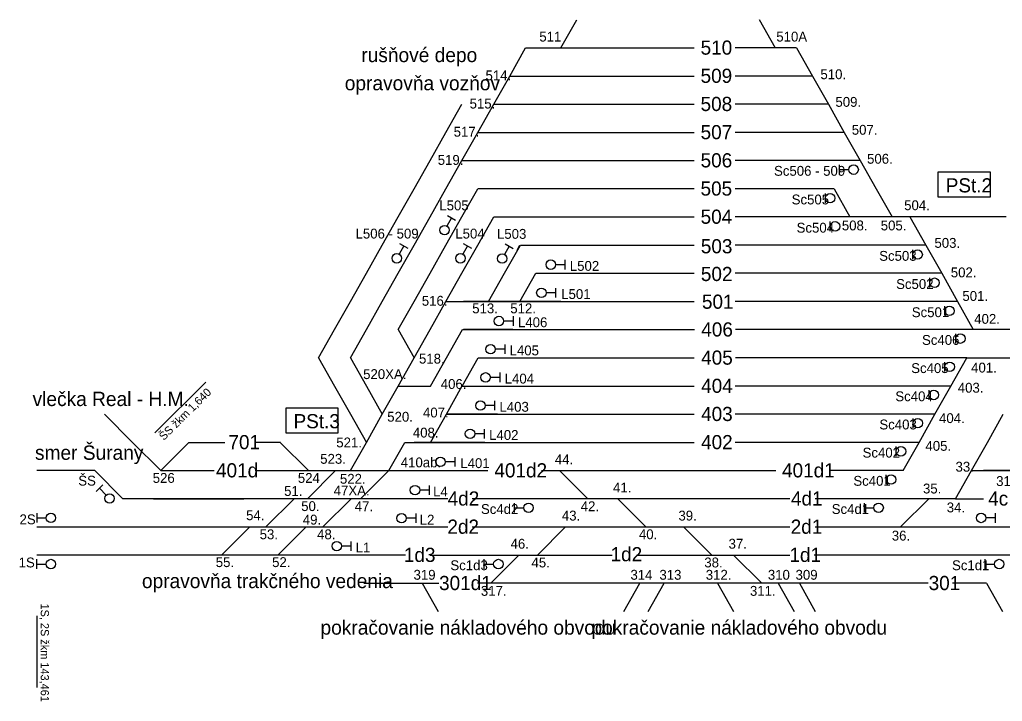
# Model space of a CAD drawing. Extents: x -119 to 851, y -238 to 59.
# Drawn here: x -82.9 to -13.2, y -186.9 to -138.5 of the extents above; entities that cross this region are included whole.
import ezdxf

# ---------------------------------------------------------------- set-up
doc = ezdxf.new("R2010")
doc.units = 0
for name, color, linetype in [('budova', 7, 'Continuous'), ('Level 2', 7, 'Continuous'), ('netlač', 7, 'Continuous'), ('popisky navestidla', 7, 'Continuous'), ('PU_navestidla', 7, 'Continuous'), ('PU_oznacenie navestidiel', 7, 'Continuous'), ('PU_stan_kolaje', 7, 'Continuous'), ('PU_vlecky', 7, 'Continuous')]:
    doc.layers.add(name, color=color, linetype=linetype)

msp = doc.modelspace()

# ---------------------------------------------------------------- linework, layer by layer
at = {"layer": 'budova'}
for points in [[(-17.784, -151.091), (-14.056, -151.091), (-14.056, -149.343), (-17.784, -149.343)], [(-64.061, -167.819), (-60.333, -167.819), (-60.333, -166.071), (-64.061, -166.071)]]:
    msp.add_lwpolyline(points, close=True, dxfattribs=at)
at = {"layer": 'Level 2'}
for p, q in [((-12.948, -152.506), (-19.775, -152.506)), ((-44.541, -158.502), (-51.44, -158.502)), ((-47.94, -160.501), (-51.44, -160.501)), ((-49.04, -166.498), (-52.662, -166.498)), ((-64.438, -168.497), (-66.22, -168.497)), ((-54.839, -168.497), (-54.939, -168.497)), ((-49.94, -168.497), (-54.839, -168.497)), ((-66.22, -170.496), (-60.529, -170.496)), ((-8.646, -170.496), (-14.545, -170.496)), ((-73.436, -172.495), (-67.037, -172.495)), ((-16.535, -172.495), (-14.54, -172.495)), ((-81.735, -174.494), (-52.567, -174.494)), ((-50.844, -174.494), (-28.284, -174.494)), ((-26.494, -174.494), (-2.882, -174.494)), ((-58.513, -178.492), (-53.203, -178.492)), ((-14.342, -178.492), (-16.745, -178.492))]:
    msp.add_line(p, q, dxfattribs=at)
for points in [[(-47.644, -154.87), (-47.44, -154.504)], [(-77.613, -170.496), (-81.735, -170.496)]]:
    msp.add_lwpolyline(points, dxfattribs=at)
at = {"layer": 'netlač'}
for p, q in [((-47.042, -140.518), (-35.082, -140.518)), ((-27.82, -140.515), (-32.169, -140.515)), ((-48.172, -142.517), (-35.082, -142.517)), ((-26.69, -142.514), (-32.169, -142.514)), ((-49.302, -144.515), (-35.082, -144.515)), ((-25.56, -144.512), (-32.169, -144.512)), ((-50.432, -146.514), (-35.082, -146.514)), ((-24.43, -146.511), (-32.169, -146.511)), ((-51.562, -148.512), (-35.082, -148.512)), ((-23.3, -148.509), (-32.169, -148.509)), ((-35.082, -150.509), (-50.432, -150.511)), ((-25.155, -150.508), (-32.169, -150.508)), ((-49.302, -152.509), (-35.082, -152.509)), ((-19.775, -152.506), (-32.169, -152.506)), ((-47.416, -154.508), (-35.082, -154.508)), ((-18.645, -154.505), (-32.169, -154.505)), ((-46.315, -156.506), (-35.082, -156.506)), ((-17.515, -156.503), (-32.169, -156.503)), ((-52.692, -158.505), (-35.082, -158.505)), ((-16.385, -158.502), (-32.169, -158.502)), ((-51.527, -160.504), (-35.066, -160.504)), ((-10.146, -160.504), (-32.152, -160.504)), ((-50.403, -162.502), (-35.07, -162.502)), ((-15.737, -162.502), (-32.157, -162.502)), ((-15.737, -162.502), (-10.885, -162.502)), ((-56.081, -164.5), (-53.787, -164.5)), ((-51.533, -164.5), (-35.074, -164.5)), ((-16.867, -164.5), (-32.161, -164.5)), ((-52.663, -166.499), (-35.078, -166.499)), ((-17.996, -166.499), (-32.165, -166.499)), ((-70.937, -168.497), (-68.377, -168.497)), ((-55.621, -168.497), (-35.082, -168.497)), ((-19.126, -168.497), (-32.169, -168.497)), ((-72.936, -170.496), (-69.147, -170.496)), ((-60.529, -170.496), (-49.712, -170.496)), ((-45.905, -170.496), (-29.297, -170.496)), ((-20.256, -170.496), (-25.438, -170.496)), ((-15.405, -170.496), (-2.882, -170.496)), ((-52.567, -172.495), (-75.614, -172.495)), ((-28.284, -172.495), (-50.844, -172.495)), ((-16.535, -172.495), (-26.49, -172.495)), ((-55.557, -176.491), (-81.735, -176.491)), ((-53.812, -176.491), (-40.889, -176.491)), ((-39.173, -176.491), (-28.284, -176.491)), ((-2.882, -176.491), (-26.561, -176.49)), ((-18.48, -178.49), (-50.454, -178.49))]:
    msp.add_line(p, q, dxfattribs=at)
at = {"layer": 'popisky navestidla'}
for p, q in [((-73.348, -167.816), (-69.736, -164.229)), ((-81.735, -180.804), (-81.735, -185.895))]:
    msp.add_line(p, q, dxfattribs=at)
at = {"layer": 'PU_navestidla'}
for p, q in [((-24.776, -149.49), (-24.776, -148.818)), ((-24.776, -149.153), (-24.104, -149.153)), ((-25.769, -151.513), (-25.769, -150.841)), ((-52.297, -152.569), (-52.628, -153.154)), ((-52.591, -152.403), (-52.006, -152.733)), ((-25.421, -153.513), (-25.421, -152.841)), ((-55.687, -154.567), (-56.018, -155.152)), ((-55.981, -154.401), (-55.396, -154.732)), ((-51.168, -154.567), (-51.498, -155.152)), ((-51.461, -154.401), (-50.876, -154.732)), ((-48.209, -154.586), (-48.54, -155.171)), ((-48.503, -154.42), (-47.918, -154.751)), ((-19.562, -155.512), (-19.562, -154.84)), ((-44.251, -155.895), (-44.923, -155.895)), ((-44.251, -155.558), (-44.251, -156.23)), ((-18.362, -157.51), (-18.362, -156.838)), ((-44.914, -157.556), (-44.914, -158.228)), ((-44.914, -157.893), (-45.586, -157.893)), ((-17.302, -159.509), (-17.302, -158.837)), ((-47.927, -159.555), (-47.927, -160.227)), ((-47.927, -159.892), (-48.599, -159.892)), ((-16.522, -161.475), (-16.522, -160.803)), ((-48.521, -161.553), (-48.521, -162.225)), ((-48.521, -161.891), (-49.193, -161.891)), ((-17.287, -163.474), (-17.287, -162.802)), ((-48.871, -163.552), (-48.871, -164.224)), ((-48.871, -163.889), (-49.543, -163.889)), ((-18.417, -165.472), (-18.417, -164.8)), ((-49.241, -165.889), (-49.913, -165.889)), ((-49.241, -165.552), (-49.241, -166.224)), ((-19.548, -167.471), (-19.548, -166.799)), ((-49.978, -167.887), (-50.65, -167.887)), ((-49.978, -167.55), (-49.978, -168.222)), ((-20.742, -169.47), (-20.742, -168.798)), ((-52.075, -169.885), (-52.747, -169.885)), ((-52.075, -169.548), (-52.075, -170.22)), ((-21.45, -171.468), (-21.45, -170.796)), ((-77.511, -171.994), (-77.035, -171.52)), ((-77.272, -171.756), (-76.798, -172.233)), ((-53.882, -171.883), (-54.554, -171.883)), ((-53.882, -171.545), (-53.882, -172.217)), ((-47.838, -173.475), (-47.838, -172.803)), ((-23.001, -173.475), (-23.001, -172.803)), ((-81.735, -173.52), (-81.735, -174.192)), ((-54.835, -173.544), (-54.835, -174.216)), ((-47.838, -173.138), (-47.166, -173.138)), ((-23.001, -173.138), (-22.329, -173.138)), ((-13.713, -173.521), (-13.713, -174.193)), ((-81.735, -173.857), (-81.063, -173.857)), ((-54.835, -173.882), (-55.507, -173.882)), ((-13.713, -173.859), (-14.385, -173.859)), ((-59.434, -175.519), (-59.434, -176.191)), ((-59.434, -175.857), (-60.106, -175.857)), ((-81.735, -177.464), (-81.735, -176.792)), ((-49.984, -177.463), (-49.984, -176.791)), ((-14.443, -177.463), (-14.443, -176.791)), ((-81.735, -177.127), (-81.063, -177.127)), ((-49.984, -177.126), (-49.312, -177.126)), ((-14.443, -177.126), (-13.771, -177.126))]:
    msp.add_line(p, q, dxfattribs=at)
for centre in [(-23.768, -149.154), (-25.433, -151.177), (-52.795, -153.445), (-25.085, -153.177), (-56.185, -155.444), (-51.665, -155.444), (-48.706, -155.463), (-19.226, -155.176), (-45.259, -155.893), (-18.026, -157.174), (-45.922, -157.892), (-16.966, -159.173), (-48.935, -159.891), (-16.186, -161.139), (-49.529, -161.889), (-16.951, -163.138), (-49.879, -163.888), (-18.081, -165.136), (-50.249, -165.888), (-19.212, -167.135), (-50.986, -167.886), (-20.406, -169.134), (-53.083, -169.884), (-21.114, -171.132), (-76.563, -172.472), (-54.89, -171.881), (-46.83, -173.139), (-21.993, -173.139), (-80.727, -173.856), (-55.843, -173.88), (-14.721, -173.857), (-60.442, -175.855), (-80.727, -177.128), (-48.976, -177.127), (-13.435, -177.127)]:
    msp.add_circle(centre, 0.336, dxfattribs=at)
at = {"layer": 'PU_stan_kolaje'}
msp.add_line((-77.613, -170.496), (-77.613, -170.496), dxfattribs=at)
for points in [[(-44.531, -140.518), (-43.401, -138.52)], [(-30.472, -138.517), (-29.342, -140.515)], [(-48.172, -142.517), (-47.042, -140.518)], [(-27.82, -140.515), (-26.69, -142.514)], [(-49.302, -144.515), (-48.172, -142.517)], [(-26.69, -142.514), (-25.56, -144.512)], [(-52.692, -146.514), (-51.562, -144.515)], [(-50.432, -146.514), (-49.302, -144.515)], [(-25.56, -144.512), (-24.43, -146.511)], [(-53.822, -148.512), (-52.692, -146.514)], [(-51.562, -148.512), (-50.432, -146.514)], [(-24.43, -146.511), (-23.3, -148.509)], [(-54.952, -150.511), (-53.822, -148.512)], [(-52.692, -150.511), (-51.562, -148.512)], [(-23.3, -148.509), (-22.17, -150.508)], [(-56.081, -152.509), (-54.952, -150.511)], [(-53.822, -152.509), (-52.692, -150.511)], [(-51.562, -152.509), (-50.432, -150.511)], [(-25.155, -150.508), (-24.025, -152.506)], [(-22.17, -150.508), (-21.04, -152.506)], [(-57.211, -154.508), (-56.081, -152.509)], [(-54.952, -154.508), (-53.822, -152.509)], [(-52.692, -154.508), (-51.562, -152.509)], [(-50.432, -154.508), (-49.302, -152.509)], [(-19.775, -152.506), (-18.645, -154.505)], [(-58.341, -156.506), (-57.211, -154.508)], [(-56.081, -156.506), (-54.952, -154.508)], [(-53.822, -156.506), (-52.692, -154.508)], [(-51.562, -156.506), (-50.432, -154.508)], [(-48.546, -156.506), (-47.416, -154.508)], [(-18.645, -154.505), (-17.515, -156.503)], [(-59.471, -158.505), (-58.341, -156.506)], [(-57.211, -158.505), (-56.081, -156.506)], [(-54.952, -158.505), (-53.822, -156.506)], [(-52.692, -158.505), (-51.562, -156.506)], [(-49.676, -158.505), (-48.546, -156.506)], [(-47.445, -158.505), (-46.315, -156.506)], [(-17.515, -156.503), (-16.385, -158.502)], [(-60.601, -160.503), (-59.471, -158.505)], [(-58.341, -160.503), (-57.211, -158.505)], [(-56.081, -160.503), (-54.952, -158.505)], [(-53.822, -160.503), (-52.692, -158.505)], [(-16.404, -158.502), (-15.274, -160.501)], [(-61.731, -162.502), (-60.601, -160.503)], [(-59.471, -162.502), (-58.341, -160.503)], [(-56.081, -160.503), (-54.952, -162.502)], [(-54.952, -162.502), (-53.822, -160.503)], [(-52.657, -162.502), (-51.527, -160.503)], [(-61.731, -162.502), (-60.601, -164.5)], [(-59.471, -162.502), (-58.341, -164.5)], [(-56.081, -164.5), (-54.952, -162.502)], [(-53.787, -164.5), (-52.657, -162.502)], [(-51.533, -164.5), (-50.403, -162.501)], [(-16.866, -164.5), (-15.736, -162.501)], [(-60.601, -164.5), (-59.471, -166.499)], [(-58.341, -164.5), (-57.211, -166.499)], [(-57.211, -166.499), (-56.081, -164.5)], [(-52.662, -166.498), (-51.532, -164.499)], [(-17.996, -166.498), (-16.866, -164.5)], [(-76.934, -166.498), (-74.935, -168.497)], [(-59.471, -166.499), (-58.341, -168.497)], [(-58.341, -168.497), (-57.211, -166.499)], [(-53.793, -168.497), (-52.663, -166.499)], [(-19.126, -168.497), (-17.996, -166.498)], [(-14.275, -168.498), (-13.145, -166.499)], [(-74.935, -168.497), (-72.936, -170.496)], [(-70.937, -168.497), (-72.936, -170.496)], [(-64.451, -168.497), (-62.452, -170.496)], [(-59.471, -170.496), (-58.341, -168.497)], [(-56.751, -170.496), (-55.621, -168.497)], [(-20.256, -170.495), (-19.126, -168.497)], [(-15.405, -170.496), (-14.275, -168.498)], [(-77.613, -170.496), (-75.614, -172.495)], [(-60.529, -170.496), (-62.528, -172.495)], [(-56.751, -170.496), (-58.75, -172.495)], [(-44.63, -170.494), (-42.631, -172.493)], [(-16.535, -172.495), (-15.405, -170.496)], [(-63.475, -172.495), (-65.474, -174.494)], [(-59.42, -172.495), (-61.419, -174.494)], [(-40.5, -172.493), (-38.5, -174.494)], [(-18.437, -172.495), (-20.436, -174.494)], [(-66.615, -174.494), (-68.59, -176.468)], [(-62.616, -174.494), (-64.591, -176.468)], [(-44.21, -174.494), (-46.208, -176.491)], [(-35.836, -174.494), (-33.839, -176.491)], [(-47.521, -176.491), (-49.52, -178.49)], [(-32.279, -176.491), (-30.28, -178.49)], [(-54.38, -178.489), (-53.25, -180.488)], [(-40.067, -180.488), (-38.937, -178.49)], [(-38.335, -180.488), (-37.205, -178.49)], [(-33.421, -178.489), (-32.291, -180.488)], [(-29.121, -178.489), (-27.991, -180.488)], [(-27.618, -178.489), (-26.488, -180.488)], [(-14.343, -178.489), (-13.213, -180.488)]]:
    msp.add_lwpolyline(points, dxfattribs=at)

# ---------------------------------------------------------------- texts
at = {"layer": 'budova'}
for s, p in [('PSt.2', (-17.227, -150.77)), ('PSt.3', (-63.508, -167.498))]:
    msp.add_text(s, height=1.0044, dxfattribs=at).set_placement(p)
at = {"layer": 'popisky navestidla'}
for s, rotation, p in [('ŠS žkm 1,640', 44.80302, (-72.714, -168.399)), ('1S, 2S žkm 143,461', 270, (-81.446, -179.927))]:
    msp.add_text(s, height=0.57931, rotation=rotation, dxfattribs=at).set_placement(p)
at = {"layer": 'PU_oznacenie navestidiel'}
for s, p in [('511', (-46.069, -140.07)), ('510A', (-29.253, -140.07)), ('514.', (-49.887, -142.819)), ('510.', (-26.123, -142.739)), ('515.', (-51.017, -144.818)), ('509.', (-25.057, -144.699)), ('517.', (-52.147, -146.816)), ('507.', (-23.897, -146.679)), ('519.', (-53.277, -148.815)), ('506.', (-22.812, -148.735)), ('Sc506 - 509', (-29.413, -149.589)), ('Sc505', (-28.161, -151.621)), ('L505', (-53.164, -152.042)), ('504.', (-20.18, -152.03)), ('L506 - 509', (-59.109, -154.041)), ('L504', (-52.031, -154.041)), ('L503', (-49.072, -154.06)), ('Sc504', (-27.811, -153.622)), ('508.', (-24.601, -153.463)), ('505.', (-21.842, -153.463)), ('503.', (-18.031, -154.7)), ('Sc503', (-21.952, -155.62)), ('L502', (-43.904, -156.332)), ('502.', (-16.87, -156.793)), ('Sc502', (-20.75, -157.618)), ('516.', (-54.407, -158.807)), ('L501', (-44.514, -158.33)), ('501.', (-16.048, -158.464)), ('513.', (-50.83, -159.342)), ('512.', (-48.129, -159.342)), ('Sc501', (-19.637, -159.617)), ('L406', (-47.582, -160.329)), ('402.', (-15.207, -160.09)), ('Sc406', (-18.912, -161.584)), ('L405', (-48.178, -162.327)), ('518.', (-54.607, -162.909)), ('Sc405', (-19.68, -163.582)), ('401.', (-15.427, -163.545)), ('520XA.', (-58.57, -164.008)), ('L404', (-48.525, -164.326)), ('406.', (-53.063, -164.708)), ('403.', (-16.375, -164.973)), ('Sc404', (-20.807, -165.581)), ('L403', (-48.896, -166.326)), ('520.', (-56.861, -167.031)), ('407.', (-54.324, -166.731)), ('404.', (-17.704, -167.129)), ('Sc403', (-21.938, -167.58)), ('408.', (-55.042, -168.156)), ('L402', (-49.63, -168.324)), ('521.', (-60.475, -168.854)), ('405.', (-18.67, -169.095)), ('523.', (-61.617, -170.016)), ('44.', (-44.968, -170.054)), ('Sc402', (-23.129, -169.578)), ('410ab.', (-55.899, -170.27)), ('L401', (-51.675, -170.322)), ('33.', (-16.534, -170.573)), ('ŠS', (-78.784, -171.563)), ('526', (-73.502, -171.37)), ('524', (-63.204, -171.37)), ('522.', (-60.217, -171.431)), ('41.', (-40.838, -172.053)), ('Sc401', (-23.784, -171.576)), ('35.', (-18.844, -172.122)), ('31.', (-13.651, -171.593)), ('51.', (-64.177, -172.295)), ('47XA.', (-60.66, -172.261)), ('L4', (-53.604, -172.331)), ('50.', (-62.966, -173.369)), ('47.', (-59.166, -173.381)), ('Sc4d2', (-50.21, -173.575)), ('42.', (-43.13, -173.379)), ('Sc4d1', (-25.32, -173.575)), ('34.', (-17.157, -173.463)), ('2S', (-82.952, -174.306)), ('54.', (-66.874, -174.017)), ('49.', (-62.852, -174.327)), ('L2', (-54.555, -174.33)), ('43.', (-44.469, -174.04)), ('39.', (-36.198, -174.04)), ('53.', (-65.913, -175.368)), ('48.', (-61.835, -175.368)), ('40.', (-39, -175.367)), ('36.', (-21.058, -175.462)), ('L1', (-59.101, -176.305)), ('46.', (-48.108, -176.039)), ('37.', (-32.639, -176.039)), ('1S', (-83.015, -177.367)), ('55.', (-69.029, -177.343)), ('52.', (-65.03, -177.343)), ('Sc1d3', (-52.378, -177.562)), ('45.', (-46.624, -177.366)), ('38.', (-34.36, -177.366)), ('Sc1d1', (-16.782, -177.562)), ('319', (-54.993, -178.241)), ('314', (-39.601, -178.241)), ('313', (-37.547, -178.241)), ('312.', (-34.257, -178.241)), ('310', (-29.851, -178.241)), ('309', (-27.885, -178.241)), ('317.', (-50.217, -179.38)), ('311.', (-31.123, -179.38))]:
    msp.add_text(s, height=0.7, dxfattribs=at).set_placement(p)
at = {"layer": 'PU_stan_kolaje'}
for s, p in [('510', (-34.623, -141)), ('509', (-34.626, -142.999)), ('508', (-34.626, -144.997)), ('507', (-34.624, -146.996)), ('506', (-34.624, -148.994)), ('505', (-34.628, -150.994)), ('504', (-34.623, -152.994)), ('503', (-34.608, -155.089)), ('502', (-34.605, -157.056)), ('501', (-34.529, -159.022)), ('406', (-34.575, -160.989)), ('405', (-34.583, -162.987)), ('404', (-34.583, -164.986)), ('403', (-34.587, -166.984)), ('701', (-68.128, -168.982)), ('402', (-34.588, -168.982)), ('401d', (-69.009, -170.982)), ('401d2', (-49.255, -170.983)), ('401d1', (-28.845, -170.981)), ('4d2', (-52.573, -172.981)), ('4d1', (-28.21, -172.98)), ('4c', (-14.218, -172.98)), ('2d2', (-52.591, -174.978)), ('2d1', (-28.232, -174.978)), ('1d3', (-55.679, -176.976)), ('1d2', (-41.012, -176.932)), ('1d1', (-28.323, -176.976)), ('301d1', (-53.182, -178.974)), ('301', (-18.442, -178.975))]:
    msp.add_text(s, height=1.0044, dxfattribs=at).set_placement(p)
at = {"layer": 'PU_vlecky'}
for s, p in [('rušňové depo', (-58.701, -141.528)), ('opravovňa vozňov', (-59.874, -143.525)), ('vlečka Real - H.M.', (-82.027, -165.923)), ('smer Šurany', (-81.857, -169.735)), ('opravovňa trakčného vedenia', (-74.268, -178.835)), ('pokračovanie nákladového obvodu', (-61.595, -182.136)), ('pokračovanie nákladového obvodu', (-42.368, -182.136))]:
    msp.add_text(s, height=1.015, dxfattribs=at).set_placement(p)

doc.saveas('drawing.dxf')
